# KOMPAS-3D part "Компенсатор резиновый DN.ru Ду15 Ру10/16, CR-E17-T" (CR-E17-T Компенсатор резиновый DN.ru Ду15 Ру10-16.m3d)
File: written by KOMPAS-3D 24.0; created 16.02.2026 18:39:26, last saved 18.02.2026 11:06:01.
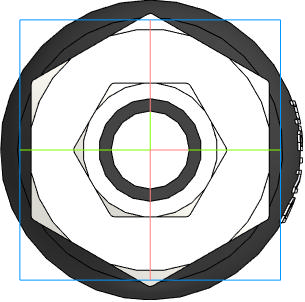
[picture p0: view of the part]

Document properties: Автор: DN.RU; Полное имя файла: CR-E17-T Компенсатор резиновый DN.ru Ду15 Ру10-16.cdw

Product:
- Body: Твердое тело1  | qty 1
    Масса: 2.112779
- Part/product: Компенсатор резиновый DN.ru Ду15 Ру10/16  | designation CR-E17-T
    Масса: 0.52
    Раздел спецификации: Прочие изделия
    Форматы листов документа: A3
    Комментарий: D140-02209
    Примечание: D140-02209
    additional columns: Типовые

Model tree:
1. Твердое тело1  (labels: Твердое тело1)

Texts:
  CR-E17-T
